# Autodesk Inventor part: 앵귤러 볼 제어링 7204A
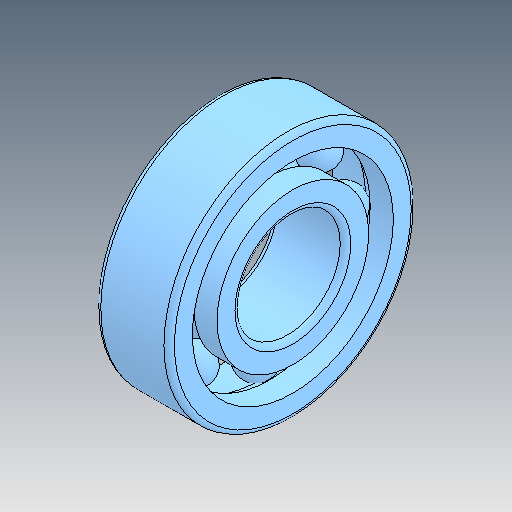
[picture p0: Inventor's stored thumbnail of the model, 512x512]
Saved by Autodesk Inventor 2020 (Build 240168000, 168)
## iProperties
Created: 2024-11
Part Number: 앵귤러 볼 제어링 7204A
Material: 강철, 연강
Description: 앵귤러 콘택트 볼 베어링
Document SubType Name: Modeling
Designer: shin
Density: 7.85 g/cm^3
Appearance: 기본값
Author: jhkim
Sending System: Autodesk Inventor 2025
Preprocessor: ST-DEVELOPER v20
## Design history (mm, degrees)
feature "Solid1"
feature "Solid1:1"
feature "Solid1:2"
feature "Solid1:3"
feature "Solid1:4"
feature "Solid1:5"
feature "Solid1:6"
feature "Solid1:7"
feature "Solid1:8"
feature "Solid1:9"
node "솔리드1"
node "솔리드2"
node "솔리드3"
node "솔리드4"
node "솔리드5"
node "솔리드6"
node "솔리드7"
node "솔리드8"
node "솔리드9"
node "솔리드10"
